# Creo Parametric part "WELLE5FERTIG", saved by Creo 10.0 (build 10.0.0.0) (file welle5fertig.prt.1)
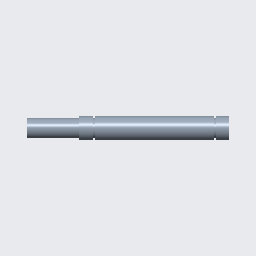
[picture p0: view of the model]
Units: millimeter Newton Second (mmNs); MM, TONNE, SECS

Created from: XX_INLBS_PART_SOLID_ABS.PRT

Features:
  1. datum plane "RIGHT"
  2. datum plane "TOP"
  3. datum plane "FRONT"
  4. coordinate system
  5. extrusion "Profil 1"
  6. extrusion "Profil 2"
  7. datum plane "DTM1"
  8. sketch "Skizze 1"
  9. sketch "Skizze 2"
  10. sketch "Skizze 3"
  11. sketch "Skizze 4"
  12. sketch "Skizze 5"
  13. sketch "Skizze 6"
  14. revolved cut "Drehen 1"
  15. sketch "Skizze 7"
  16. revolved cut "Drehen 2"

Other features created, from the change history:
  curve "Schneiden 1"
  sketch "Skizze 1" (4 times)
  revolved cut "Drehen 1" (2 times)
  feature "Drehen 1"
  revolved cut "Drehen 2"

Surfaces: 7 plane, 6 cylinder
